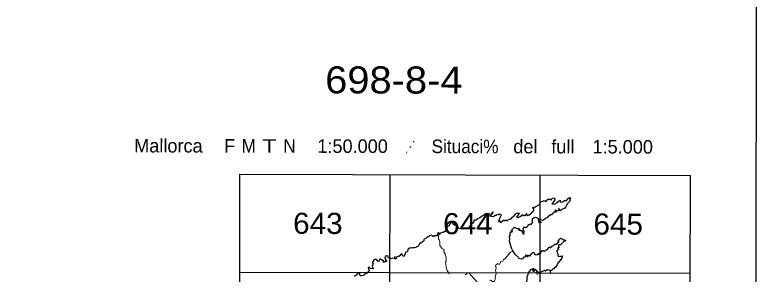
# Model space of a CAD drawing. Extents: x 480264 to 484872, y 4381275 to 4384491.
# Drawn here: x 484186 to 484872, y 4383525 to 4383765 of the extents above; entities that cross this region are included whole.
import ezdxf
from ezdxf.enums import TextEntityAlignment as Align

# ---------------------------------------------------------------- set-up
doc = ezdxf.new("R2010")
doc.units = 0
doc.header["$LTSCALE"] = 4
doc.linetypes.add('DOTTED', pattern=[1.5, 0.3, -1.2])
for name, color, linetype, lineweight in [('1', 7, 'Continuous', 13), ('2', 7, 'DOTTED', 13), ('3', 7, 'Continuous', 25)]:
    doc.layers.add(name, color=color, linetype=linetype, lineweight=lineweight)

msp = doc.modelspace()

# ---------------------------------------------------------------- linework, layer by layer
at = {"layer": '1', "lineweight": 25}
for p, q in [((484392.94, 4383256.25), (484393.8, 4383617.56)), ((484393.8, 4383617.55), (484809.48, 4383616.56)), ((484531.07, 4383075.28), (484532.36, 4383617.23)), ((484669.63, 4383074.95), (484670.92, 4383616.9)), ((484808.41, 4383164.93), (484809.48, 4383616.57)), ((484393.59, 4383527.22), (484809.26, 4383526.23))]:
    msp.add_line(p, q, dxfattribs=at)
msp.add_lwpolyline([(480271.92, 4384491.35), (484871.91, 4384480.42), (484864.3, 4381275.43), (480264.31, 4381286.36)], close=True, dxfattribs=at)
at = {"layer": '2'}
msp.add_line((484547.36, 4383637.19), (484556.71, 4383651.47), dxfattribs=at)
at = {"layer": '3', "lineweight": 13}
msp.add_line((484586.31, 4383526.7), (484586.91, 4383525.19), dxfattribs=at)
at = {"layer": '3'}
msp.add_line((484670.57, 4383526.83), (484669.78, 4383526.52), dxfattribs=at)
for points in [[(484670.62, 4383591.56), (484674.37, 4383593.43), (484675.02, 4383592.9), (484675.65, 4383593.31), (484675.51, 4383592.61), (484675.93, 4383592.35), (484677.25, 4383593.52), (484677.59, 4383594.36), (484678.78, 4383594.78), (484678.61, 4383594.22), (484680.46, 4383594.5), (484680.57, 4383593.74), (484681.02, 4383593.97), (484681.3, 4383594.91), (484683.06, 4383595.87), (484684.12, 4383595.36), (484684.26, 4383593.98), (484683.26, 4383592.82)], [(484692.16, 4383592.57), (484693.36, 4383593.2), (484695.03, 4383593.4), (484696.7, 4383595.32), (484697.97, 4383596.07), (484698.63, 4383595.65), (484697.91, 4383594.28), (484698.37, 4383593.86), (484697.95, 4383592.25), (484696.1, 4383590.67), (484694.73, 4383588.46), (484694.6, 4383587.2), (484693.71, 4383586.71), (484693.38, 4383585.92)], [(484670.62, 4383591.56), (484670.19, 4383591.14), (484670.4, 4383590.59), (484669.72, 4383589.24), (484668.11, 4383588.46), (484667.45, 4383587.64), (484666.62, 4383587.52), (484665.9, 4383586.81), (484665.41, 4383587.06), (484664.62, 4383586.37), (484664.62, 4383584.54), (484664.13, 4383582.99), (484662.7, 4383582.04), (484662.38, 4383581.3), (484660.33, 4383579.6), (484659.72, 4383579.62), (484659.42, 4383579.22), (484658.96, 4383579.6)], [(484683.26, 4383592.82), (484682.41, 4383591.14), (484681.45, 4383590.29), (484682.5, 4383590.39), (484684.04, 4383589.89), (484685.25, 4383590.42), (484686.16, 4383591.59), (484689.34, 4383593.71), (484689.4, 4383591.71), (484691.45, 4383592.02), (484692.16, 4383592.57)], [(484629.26, 4383579.54), (484627.85, 4383578.32), (484625.22, 4383578.66), (484625.81, 4383580.44), (484627.32, 4383582.03), (484627.22, 4383582.73), (484625.46, 4383581.03), (484625.02, 4383579.61), (484623.45, 4383578.72), (484622.6, 4383579.12), (484622.57, 4383579.6), (484624.02, 4383581.04), (484622, 4383581.07)], [(484693.38, 4383585.92), (484691.01, 4383585.19), (484689.6, 4383583.78), (484688.08, 4383586.04), (484687.58, 4383585.49), (484688.05, 4383584.91), (484687.88, 4383584.13), (484686.04, 4383583.59), (484685, 4383584.26), (484684.46, 4383584.15), (484685.8, 4383582.68), (484683.53, 4383582.44), (484682.74, 4383581.35), (484682.1, 4383581.36)], [(484622, 4383581.07), (484621.29, 4383581.25), (484614.51, 4383576.85), (484613.08, 4383576.35), (484612.83, 4383576.64), (484612.58, 4383575.83), (484611.83, 4383575.3), (484610.21, 4383575.23), (484609.26, 4383573.78), (484609.14, 4383572.8), (484608.28, 4383572.08), (484607.31, 4383571.8)], [(484635.73, 4383573.85), (484634.52, 4383572.84), (484634.44, 4383573.18), (484633.53, 4383573.2), (484634.05, 4383574.26), (484632.91, 4383573.58), (484632.38, 4383574.21), (484633.33, 4383575.48), (484633.59, 4383576.98), (484635.03, 4383579.96), (484634.1, 4383579.71), (484634.01, 4383580.27), (484633.31, 4383580.56), (484632.33, 4383580.12), (484631.15, 4383580.31), (484630.25, 4383579.54), (484629.26, 4383579.54)], [(484650.29, 4383581.46), (484649.43, 4383581.76), (484648.13, 4383581.14), (484645.77, 4383578.13), (484645, 4383577.95), (484643.13, 4383575.77), (484642.67, 4383575.96), (484641.37, 4383575.39), (484640, 4383574.29), (484639.7, 4383574.8), (484638.83, 4383574.96), (484637.97, 4383574.34), (484637.71, 4383574.76), (484636.93, 4383574.72), (484635.73, 4383573.85)], [(484658.96, 4383579.6), (484658.51, 4383580.23), (484658.52, 4383581.24), (484656.68, 4383579.15), (484655.96, 4383579.72), (484655.05, 4383579.16), (484654.67, 4383579.19), (484654.62, 4383579.64), (484653.57, 4383579.74), (484652.51, 4383578.63), (484650.08, 4383577.38), (484648.92, 4383578.18), (484649.92, 4383578.84), (484651.78, 4383581.29), (484650.61, 4383581.72), (484650.29, 4383581.46)], [(484670.6, 4383575.11), (484669.72, 4383575.27), (484669, 4383576.58), (484667.78, 4383577.22), (484666.55, 4383577.48), (484664.53, 4383576.96), (484663.49, 4383575.96), (484663.25, 4383572.4), (484662.56, 4383571.7)], [(484682.1, 4383581.36), (484681.17, 4383580.15), (484680.32, 4383580.09), (484678.51, 4383578.48), (484677.44, 4383578.38), (484677.8, 4383577.73), (484675.79, 4383576.63), (484673.63, 4383574.8), (484671.34, 4383575.6), (484670.6, 4383575.11)], [(484587.78, 4383571.86), (484587.38, 4383571.7), (484586.88, 4383570.05), (484585.16, 4383569.22), (484584.12, 4383567.46), (484583.24, 4383564.59), (484582.35, 4383564.5), (484581.34, 4383563.6), (484580.74, 4383563.72), (484578.91, 4383563.01), (484578.52, 4383562.53)], [(484587.78, 4383571.86), (484589.12, 4383573.34), (484589.89, 4383572.82), (484590.16, 4383571.85)], [(484590.16, 4383571.85), (484590.58, 4383571.36), (484591.58, 4383571.48), (484591.94, 4383570.57), (484593, 4383570.76), (484593.67, 4383570.01), (484594.62, 4383570.25), (484594.22, 4383569.17), (484595.61, 4383567.84), (484597.53, 4383567.31), (484598.61, 4383568.06), (484599.19, 4383567.84), (484599.38, 4383567.22), (484599.8, 4383567.56), (484600.26, 4383567.15), (484601.56, 4383567.5)], [(484607.31, 4383571.8), (484607.11, 4383570.38), (484606.33, 4383570.33), (484604.25, 4383567.42), (484603.43, 4383567.17), (484603.03, 4383567.45), (484602.69, 4383567), (484601.56, 4383567.5)], [(484651.03, 4383565.98), (484652.3, 4383565.97), (484651.44, 4383567.07), (484651.02, 4383567.23), (484650.73, 4383566.39), (484650.74, 4383567.36), (484649.58, 4383567.19), (484647.43, 4383568.24), (484646.4, 4383568.17), (484644.24, 4383565.86), (484644.95, 4383565.42), (484644.89, 4383564.88), (484644.13, 4383565.54), (484643.92, 4383565.1), (484644.46, 4383564.91), (484643.82, 4383564.95), (484644.45, 4383564.61), (484643.71, 4383564.78), (484644.74, 4383564.39), (484645.26, 4383564.76), (484644.87, 4383564.28)], [(484662.56, 4383571.7), (484661.89, 4383570.99), (484660.96, 4383571.01), (484659.34, 4383570.24), (484658.75, 4383568.85), (484657.51, 4383567.98), (484655.56, 4383568.65), (484655.26, 4383568.45), (484654.71, 4383566.69), (484655.69, 4383564.6), (484655.46, 4383561.81), (484654.18, 4383565.4), (484653.03, 4383565.22), (484652.34, 4383565.84), (484651.03, 4383565.98)], [(484670.6, 4383574.07), (484670.02, 4383574.66), (484669.44, 4383574.57), (484669.32, 4383574.16), (484669.58, 4383573.37), (484670.6, 4383572.76)], [(484670.6, 4383574.07), (484671.54, 4383573.88), (484671.85, 4383573.11), (484670.6, 4383572.76)], [(484578.52, 4383562.53), (484578.27, 4383562.85), (484577.49, 4383562.78), (484576.61, 4383563.58), (484576.13, 4383563.22), (484576.21, 4383562.55), (484575.76, 4383561.92), (484575.92, 4383560.94), (484575.45, 4383560.65), (484574.6, 4383560.71), (484574.43, 4383561.08), (484573.89, 4383560.48), (484573.32, 4383560.68), (484571.75, 4383559.87), (484571.19, 4383560.89), (484570.12, 4383561.24), (484568.67, 4383560.75), (484567.62, 4383559.81), (484566.78, 4383559.89)], [(484644.87, 4383564.28), (484644.71, 4383563.7), (484643.6, 4383564.58), (484643.21, 4383563.45), (484642.8, 4383563.35), (484642.65, 4383560.89), (484642.13, 4383560), (484642.43, 4383557.86), (484642.13, 4383556.17), (484644, 4383549.69), (484645.64, 4383546.49)], [(484566.78, 4383559.89), (484565.4, 4383558.18), (484563.75, 4383557.72), (484563.35, 4383557), (484563.53, 4383556.15), (484562.88, 4383555.33), (484559.56, 4383553.23), (484558.92, 4383551.94), (484558.41, 4383551.87), (484558.06, 4383550.75)], [(484680.22, 4383549.23), (484680.86, 4383550.95), (484681.34, 4383550.23), (484681.94, 4383551.16), (484683.3, 4383551.88), (484684.13, 4383553.11), (484684.25, 4383552.86), (484685.42, 4383553.12), (484686.74, 4383553.81), (484687.14, 4383554.63), (484688.06, 4383554.69), (484687.79, 4383554.91), (484688.31, 4383555.25), (484687.46, 4383555.38), (484687.79, 4383555.69), (484687.37, 4383555.73), (484687.53, 4383556.15)], [(484687.53, 4383556.15), (484687.66, 4383556.7), (484688.38, 4383556.78), (484688.14, 4383557.09), (484688.49, 4383557.16), (484688.48, 4383558.05), (484688.93, 4383557.87), (484690.23, 4383558.56), (484691.21, 4383558.05), (484691.67, 4383557.23), (484692.24, 4383557.1), (484692.67, 4383557.48), (484693.03, 4383556.82), (484693.89, 4383556.99), (484694.26, 4383556.35), (484694.12, 4383555.78), (484693.05, 4383555.65), (484689.65, 4383552.46), (484688.89, 4383552.28)], [(484558.06, 4383550.75), (484556.76, 4383550.55), (484556.17, 4383549.84), (484555, 4383549.67), (484554.66, 4383549.94), (484554.33, 4383549.44), (484553.02, 4383549.62), (484552.22, 4383549.18), (484551.23, 4383549.46), (484550.06, 4383548.93), (484549.26, 4383549.01), (484548.55, 4383548), (484548.36, 4383546.12), (484546.65, 4383545.26), (484545.42, 4383541.84), (484544.28, 4383541.5), (484543.34, 4383543.37)], [(484670.58, 4383544.17), (484671.31, 4383544.51), (484671.64, 4383545.88), (484672.77, 4383547.15), (484673.42, 4383546.99), (484673.52, 4383546.63), (484674.13, 4383546.83), (484674.7, 4383546.5), (484675.17, 4383547.04), (484675.57, 4383546.86), (484675.89, 4383547.68), (484676.03, 4383547.39), (484677.54, 4383548.04), (484678.08, 4383549.46), (484678.66, 4383549.48), (484678.78, 4383550.12), (484679.47, 4383550.12), (484680.22, 4383549.23)], [(484688.89, 4383552.28), (484687.62, 4383552.27), (484687.74, 4383550.88), (484688.61, 4383549.91), (484687.11, 4383549.73), (484687.04, 4383548.95), (484687.82, 4383547.93), (484687.16, 4383547.7), (484685.97, 4383546.4), (484686.69, 4383545.97), (484686.46, 4383545.42), (484687.27, 4383543.02), (484686.94, 4383542.59), (484687.13, 4383542.06), (484687.55, 4383541.61), (484689.07, 4383542.01), (484689.39, 4383541.76), (484689.8, 4383542), (484690.15, 4383541.59)], [(484532.4, 4383540.07), (484530.4, 4383540.23), (484530.86, 4383541.32), (484530.5, 4383542), (484528.5, 4383542.12), (484527.78, 4383541.4), (484527.45, 4383540.11), (484527.96, 4383539.25), (484528.67, 4383539.14), (484528.17, 4383538.36), (484528.55, 4383537.84), (484528.88, 4383538.03), (484528.98, 4383536.99), (484528.36, 4383536.82), (484527.69, 4383537.15), (484526.72, 4383536.11), (484526.35, 4383536.4), (484526.32, 4383537.45), (484525.41, 4383538.14), (484524.64, 4383538.18), (484523.67, 4383539.03)], [(484543.34, 4383543.37), (484542.61, 4383543.92), (484541.41, 4383542.32), (484540.94, 4383542.41), (484540.32, 4383541.65), (484539.5, 4383541.67), (484538.34, 4383541.07), (484538, 4383539.56), (484537.27, 4383539.5), (484537.09, 4383539.14), (484536.74, 4383539.71), (484537.11, 4383541.18), (484536.76, 4383541.45), (484536.17, 4383539.66), (484534.85, 4383540.13), (484533.25, 4383539.31), (484532.96, 4383539.93), (484532.4, 4383540.07)], [(484645.64, 4383546.49), (484647.04, 4383544.04), (484650.67, 4383540.66), (484650.58, 4383540.31), (484653.06, 4383539.29), (484655.19, 4383539.63), (484655.81, 4383541.37), (484656.6, 4383541.25), (484657.45, 4383541.71), (484657.6, 4383543.03), (484658.68, 4383542.82), (484658.62, 4383541.64), (484659.27, 4383541.47), (484659.71, 4383541.6), (484659.55, 4383542.27), (484660.32, 4383542.89)], [(484660.32, 4383542.89), (484660.98, 4383542.12), (484661.61, 4383542.25), (484662.94, 4383544.42), (484664.37, 4383545.67), (484665.31, 4383545.07), (484665.67, 4383543.6), (484666.26, 4383543.84), (484666.93, 4383543.09), (484667.47, 4383543.35), (484668.22, 4383543.08), (484669.02, 4383544.13), (484669, 4383543.3), (484669.4, 4383543.9), (484669.76, 4383543.56), (484669.96, 4383543.81), (484668.96, 4383544.5), (484670.16, 4383543.98), (484670.58, 4383544.17)], [(484690.15, 4383541.59), (484691.39, 4383542.05), (484690.84, 4383539.89), (484687.79, 4383535.95), (484687.14, 4383535.87), (484687.16, 4383535.13), (484686.55, 4383534.77), (484686.71, 4383534.37), (484684.86, 4383531.64), (484683.72, 4383530.71), (484683.68, 4383530.09), (484682.97, 4383530.25), (484682.24, 4383529.9), (484681.55, 4383528.67), (484680.22, 4383528.64), (484679.59, 4383528.18), (484678.73, 4383528.8)], [(484523.67, 4383539.03), (484522.73, 4383539.05), (484521.96, 4383537.36), (484521.2, 4383536.94), (484520.75, 4383537.85), (484519.28, 4383538.78), (484518.15, 4383538.73), (484517.1, 4383538.02), (484516.01, 4383536.21), (484516.13, 4383535.31), (484516.57, 4383535.08), (484515.88, 4383532.66), (484515.99, 4383531.62), (484516.82, 4383530.12), (484514.34, 4383530.47), (484513.39, 4383531.55)], [(484511.79, 4383527.01), (484511.32, 4383526.81), (484511.09, 4383526.11), (484508.75, 4383525.33), (484508.15, 4383524.38), (484506.02, 4383523.6), (484504.86, 4383523.64), (484504.44, 4383524.22), (484504.33, 4383526.21), (484503.9, 4383525.89), (484502.43, 4383526.12), (484501.14, 4383524.46), (484498.78, 4383523.02)], [(484513.39, 4383531.55), (484513.05, 4383531.74), (484512.19, 4383531.05), (484512.8, 4383529.44), (484512.37, 4383529), (484512.85, 4383528.49), (484512.68, 4383527.61), (484511.79, 4383527.01)], [(484660.09, 4383526.55), (484662.42, 4383529.6), (484664.33, 4383530.4), (484664.69, 4383530.38), (484664.41, 4383529.67), (484663.6, 4383528.98), (484664.39, 4383528.02), (484665.53, 4383527.95), (484664.35, 4383528.66), (484664.89, 4383530.21), (484666.37, 4383529.98), (484666.52, 4383529.55), (484665.92, 4383528.81), (484666.66, 4383529.18), (484667.91, 4383527.96), (484666.78, 4383526.81), (484667.98, 4383527.93), (484668.79, 4383527.18), (484668.89, 4383526.53)], [(484678.73, 4383528.8), (484677.36, 4383529.15), (484675.77, 4383528.04), (484674.87, 4383528.5), (484670.57, 4383526.83)], [(484660.09, 4383526.55), (484658.59, 4383522.41), (484658.06, 4383516.51)], [(484668.89, 4383526.53), (484667.86, 4383525.7), (484668.05, 4383525.32), (484669.19, 4383526.45), (484669.78, 4383526.52)]]:
    msp.add_lwpolyline(points, dxfattribs=at)
for points in [[(484664.49, 4383587.27), (484663.87, 4383586.97), (484663.6, 4383586.1), (484664.33, 4383586.31)], [(484680.02, 4383527.49), (484679.89, 4383526.87), (484680.77, 4383527.11), (484680.7, 4383527.46)]]:
    msp.add_lwpolyline(points, close=True, dxfattribs=at)
at = {"layer": '3', "lineweight": 13}
for points in [[(484578.52, 4383562.53), (484576.96, 4383561.25), (484577.11, 4383557.48), (484577.66, 4383557.05), (484578.15, 4383555.24), (484578.2, 4383551.85), (484580.38, 4383548.64), (484582.16, 4383547.89), (484582.02, 4383545.78), (484583.23, 4383544.43), (484583.17, 4383543.12), (484583.87, 4383541.52), (484584.13, 4383539.54), (484583.97, 4383537.37), (484583.39, 4383536.22), (484584.42, 4383530.25), (484585.06, 4383528.49), (484586.31, 4383526.7)], [(484645.64, 4383546.49), (484643.34, 4383545.55), (484638.84, 4383539.94), (484637.03, 4383538.5), (484636.33, 4383537.29), (484634.54, 4383536.93), (484633.36, 4383534.11), (484631.43, 4383534.99), (484630.93, 4383534.16), (484629.51, 4383533.65), (484630.03, 4383530.33), (484629.55, 4383528.83), (484630.1, 4383526.6)], [(484613.21, 4383517.13), (484606.74, 4383524.45), (484605.33, 4383526.54), (484603.81, 4383526.3), (484601.45, 4383524.68)], [(484630.1, 4383526.6), (484630.29, 4383525.77), (484629.23, 4383522.6), (484629.34, 4383520.38), (484628.54, 4383519), (484627.56, 4383517.8), (484625.39, 4383519.57), (484624.34, 4383519.48)]]:
    msp.add_lwpolyline(points, dxfattribs=at)

# ---------------------------------------------------------------- texts
at = {"layer": '2'}
for s, height, width, p in [('698-8-4', 25, 1.1, (484535.74, 4383692.217)), ('643', 19.5, 1.05, (484465.652, 4383562.454)), ('644', 19.5, 1.05, (484604.012, 4383562.134)), ('645', 19.5, 1.05, (484742.772, 4383561.804))]:
    msp.add_text(s, height=height, rotation=359.864, dxfattribs=dict(at, width=width)).set_placement(p, align=Align.CENTER)
for s, p in [('Mallorca', (484296.15, 4383637.79)), ('F', (484379.07, 4383637.59)), ('1:50.000', (484465.15, 4383637.39)), ('del', (484645.99, 4383636.96)), ('full', (484681, 4383636.88)), ('1:5.000', (484719.06, 4383636.79))]:
    msp.add_text(s, height=12.5, rotation=359.864, dxfattribs=at).set_placement(p)
for s, width, p in [('M', 0.95, (484395.23, 4383637.56)), ('T', 1.3, (484414.21, 4383637.51)), ('N', 0.95, (484433.7, 4383637.46)), ('Situaci%', 0.95, (484570.55, 4383637.14))]:
    msp.add_text(s, height=12.5, rotation=359.864, dxfattribs=dict(at, width=width)).set_placement(p)

doc.saveas('drawing.dxf')
